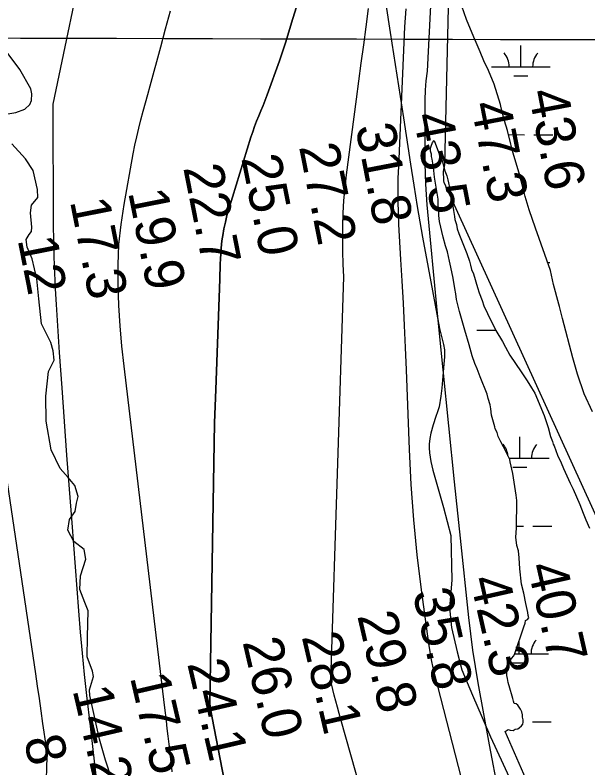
# Model space of a CAD drawing. Extents: x 3161665 to 3199565, y 885729 to 911164.
# Drawn here: x 3178214 to 3179188, y 895980 to 897260 of the extents above; entities that cross this region are included whole.
import ezdxf

# ---------------------------------------------------------------- set-up
doc = ezdxf.new("R2010")
doc.units = 0
for name, color, linetype in [('V-GRID-MAJR', 7, 'Continuous'), ('V-RIVR-EDGE', 7, 'Continuous'), ('V-RIVR-RANG', 7, 'Continuous'), ('V-SITE-VEGE', 7, 'Continuous'), ('V-TOPO-DPTH', 7, 'Continuous'), ('V-TOPO-MAJR', 7, 'Continuous'), ('V-TOPO-MINR', 7, 'Continuous'), ('V-TOPO-WATR', 7, 'Continuous'), ('V-WETL-SWMP', 7, 'Continuous')]:
    doc.layers.add(name, color=color, linetype=linetype)

msp = doc.modelspace()

# ---------------------------------------------------------------- linework, layer by layer
at = {"layer": 'V-GRID-MAJR'}
msp.add_spline([(3165896.843, 897258.21), (3171121.2120000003, 897241.873), (3176345.5840000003, 897226.295), (3181569.957, 897211.478), (3186794.333, 897197.42), (3192018.711, 897184.122), (3197243.091, 897171.584), (3197243.092, 897171.584)], degree=3, dxfattribs=at)
at = {"layer": 'V-RIVR-EDGE'}
for points in [[(3178201.617912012, 897091.790542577), (3178215.099333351, 897094.3652820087), (3178230.326984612, 897099.978457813), (3178239.0398621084, 897107.7811387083), (3178241.6651185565, 897114.7295141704), (3178242.127740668, 897126.0300290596), (3178240.844132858, 897134.2921075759), (3178221.800052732, 897167.374816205), (3178200.571841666, 897196.116133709)], [(3178378.34260989, 895960.3183127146), (3178367.556308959, 895992.9459230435), (3178357.647959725, 896029.048795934), (3178340.8782962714, 896102.9857240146), (3178340.467266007, 896112.5496824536), (3178347.04330509, 896135.1367394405), (3178345.76184694, 896144.2681710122), (3178336.2602286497, 896169.068379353), (3178336.777667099, 896202.5373971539), (3178338.191329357, 896246.8711784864), (3178332.576003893, 896261.2294766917), (3178323.937289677, 896283.4194762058), (3178324.8636087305, 896306.4551825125), (3178334.0627546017, 896335.1212619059), (3178331.494464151, 896351.210742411), (3178313.7060462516, 896364.7297828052), (3178303.322176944, 896384.3160224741), (3178306.408980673, 896402.1302362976), (3178316.006258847, 896416.01623892), (3178318.2151108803, 896430.3551901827), (3178321.285792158, 896441.6492560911), (3178315.2465384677, 896460.3553944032), (3178303.9782684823, 896473.8583123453), (3178290.54091518, 896489.1053105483), (3178275.405699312, 896520.8743161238), (3178266.8325497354, 896569.5795838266), (3178266.068530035, 896612.1800331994), (3178270.953155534, 896653.8971567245), (3178280.1297299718, 896673.4350290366), (3178278.429717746, 896689.0876833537), (3178274.5520235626, 896703.0070057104), (3178258.5485294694, 896735.2128374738), (3178254.3060227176, 896777.3872089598), (3178250.9124472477, 896811.3005767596), (3178242.7374299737, 896845.2257676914), (3178234.528018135, 896865.2413097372), (3178232.8215569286, 896878.2859048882), (3178238.059171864, 896886.9665374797), (3178241.5484072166, 896891.7393806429), (3178242.437107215, 896899.5614084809), (3178240.323915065, 896923.9086681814), (3178241.660189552, 896936.9457395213), (3178252.558272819, 896949.5244880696), (3178252.157990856, 896963.4352117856), (3178244.4133507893, 896995.6206217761), (3178231.857173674, 897015.6469121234), (3178208.4469813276, 897040.9161915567)]]:
    msp.add_lwpolyline(points, dxfattribs=at)
at = {"layer": 'V-SITE-VEGE'}
for p, q in [((3178844.216, 897278.5349999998), (3178851.311, 897230.0849999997)), ((3178851.311, 897230.0849999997), (3178874.412, 897085.0949999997)), ((3178874.412, 897085.0949999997), (3178885.9420000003, 897006.6939999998)), ((3178885.9420000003, 897006.6939999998), (3178891.607, 896970.5009999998)), ((3178891.607, 896970.5009999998), (3178897.52, 896934.3479999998)), ((3178897.52, 896934.3479999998), (3178906.453, 896882.4459999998)), ((3178906.453, 896882.4459999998), (3178915.9390000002, 896830.6369999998)), ((3178915.9390000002, 896830.6369999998), (3178935.467, 896727.1639999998)), ((3178935.467, 896727.1639999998), (3178938.8340000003, 896713.6019999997)), ((3178938.8340000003, 896713.6019999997), (3178942.434, 896700.0959999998)), ((3178942.434, 896700.0959999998), (3178943.948, 896690.9719999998)), ((3178943.948, 896690.9719999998), (3178944.1750000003, 896684.8829999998)), ((3178943.849, 896678.7659999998), (3178942.643, 896666.5229999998)), ((3178944.1750000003, 896684.8829999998), (3178943.849, 896678.7659999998)), ((3178942.643, 896666.5229999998), (3178939.536, 896625.3989999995)), ((3178939.536, 896625.3989999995), (3178937.955, 896611.7469999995)), ((3178937.955, 896611.7469999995), (3178934.693, 896593.6509999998)), ((3178932.008, 896585.5269999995), (3178928.9620000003, 896577.5349999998)), ((3178934.693, 896593.6509999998), (3178932.008, 896585.5269999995)), ((3178928.9620000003, 896577.5349999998), (3178924.588, 896563.5309999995)), ((3178924.588, 896563.5309999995), (3178920.6720000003, 896549.3219999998)), ((3178920.6720000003, 896549.3219999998), (3178918.835, 896539.9929999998)), ((3178918.835, 896539.9929999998), (3178917.936, 896530.5459999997)), ((3178917.936, 896530.5459999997), (3178917.858, 896524.2419999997)), ((3178917.858, 896524.2419999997), (3178918.401, 896515.9049999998)), ((3178918.401, 896515.9049999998), (3178920.596, 896500.9889999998)), ((3178920.596, 896500.9889999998), (3178924.017, 896486.2419999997)), ((3178924.017, 896486.2419999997), (3178933.071, 896454.4629999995)), ((3178933.071, 896454.4629999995), (3178942.393, 896422.8209999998)), ((3178942.393, 896422.8209999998), (3178954.708, 896374.8549999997)), ((3178954.708, 896374.8549999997), (3178956.631, 896299.1749999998)), ((3178956.631, 896299.1749999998), (3178954.808, 896279.3709999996)), ((3178954.808, 896279.3709999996), (3178952.639, 896252.2429999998)), ((3178952.639, 896252.2429999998), (3178955.894, 896218.6049999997)), ((3178955.894, 896218.6049999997), (3178965.657, 896177.3699999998)), ((3178965.657, 896177.3699999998), (3178973.25, 896146.9859999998)), ((3178973.25, 896146.9859999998), (3178991.693, 896103.5809999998)), ((3178991.693, 896103.5809999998), (3179007.964, 896065.6029999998)), ((3179007.964, 896065.6029999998), (3179022.069, 896033.0499999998)), ((3179022.069, 896033.0499999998), (3179043.7630000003, 895986.3879999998)), ((3179043.7630000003, 895986.3879999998), (3179069.799, 895929.9619999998))]:
    msp.add_line(p, q, dxfattribs=at)
at = {"layer": 'V-TOPO-DPTH'}
for points in [[(3178859.7052312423, 897811.8009133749), (3178683.971657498, 897246.9387973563), (3178674.1705732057, 897214.5114061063), (3178663.364810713, 897182.3625362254), (3178642.3309438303, 897124.2634451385), (3178638.9716953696, 897115.2234071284), (3178635.5116471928, 897106.2230984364), (3178631.9003994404, 897097.2823837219), (3178628.188351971, 897088.3813983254), (3178624.54341345, 897079.4579472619), (3178621.0883832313, 897070.4649463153), (3178617.918215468, 897061.3676205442), (3178614.937956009, 897052.2007448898), (3178577.3112899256, 896929.9501530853), (3178574.1741301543, 896918.887475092), (3178571.3690015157, 896907.7489882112), (3178569.061919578, 896896.4967879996), (3178567.0868687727, 896885.1687789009), (3178566.21151534, 896879.3909969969), (3178565.078478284, 896870.8807860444), (3178564.1503880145, 896862.3519970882), (3178563.5297179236, 896853.7953411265), (3178563.113994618, 896845.2201071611), (3178562.845206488, 896836.6311385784), (3178562.5667702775, 896828.0424909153), (3178562.27386195, 896819.4543246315), (3178561.9713055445, 896810.8664792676), (3178555.2151163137, 896623.5815065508), (3178552.7718726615, 896566.9030446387), (3178544.7785713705, 896089.8985583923), (3178545.67613638, 896083.7384648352), (3178546.640442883, 896077.5893959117), (3178547.7048616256, 896071.4568639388), (3178548.836021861, 896065.3353565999), (3178667.7391202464, 895449.9836645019)], [(3178367.6467745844, 895829.032779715), (3178346.644979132, 896011.4635693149), (3178345.5129858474, 896021.2999095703), (3178344.381500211, 896031.1363082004), (3178343.250776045, 896040.9727943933), (3178342.1205595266, 896050.8093389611), (3178336.1221828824, 896103.0324697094), (3178332.19636842, 896139.0001007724), (3178328.541420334, 896174.9936939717), (3178325.292771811, 896211.0262303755), (3178322.314989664, 896247.0847289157), (3178310.7941442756, 896396.8911518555), (3178306.436270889, 896454.1543789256), (3178302.1393138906, 896511.4221278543), (3178297.9337314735, 896568.6966595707), (3178293.789065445, 896625.9757131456), (3178289.466234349, 896686.3864560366), (3178287.592488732, 896713.4675927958), (3178285.8038284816, 896740.5541468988), (3178284.142796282, 896767.6488270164), (3178282.5668494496, 896794.7489244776), (3178281.2719958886, 896821.8593985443), (3178280.2666717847, 896848.9782854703), (3178279.6956418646, 896876.1097916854), (3178279.4141414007, 896903.2497107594), (3178278.92802394, 897108.7204964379), (3178395.3976408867, 897666.5492682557)], [(3178367.6467745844, 895829.032779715), (3178346.644979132, 896011.4635693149), (3178345.5129858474, 896021.2999095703), (3178344.381500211, 896031.1363082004), (3178343.250776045, 896040.9727943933), (3178342.1205595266, 896050.8093389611), (3178336.1221828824, 896103.0324697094), (3178332.19636842, 896139.0001007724), (3178328.541420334, 896174.9936939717), (3178325.292771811, 896211.0262303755), (3178322.314989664, 896247.0847289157), (3178310.7941442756, 896396.8911518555), (3178306.436270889, 896454.1543789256), (3178302.1393138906, 896511.4221278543), (3178297.9337314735, 896568.6966595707), (3178293.789065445, 896625.9757131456), (3178289.466234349, 896686.3864560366), (3178287.592488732, 896713.4675927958), (3178285.8038284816, 896740.5541468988), (3178284.142796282, 896767.6488270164), (3178282.5668494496, 896794.7489244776), (3178281.2719958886, 896821.8593985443), (3178280.2666717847, 896848.9782854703), (3178279.6956418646, 896876.1097916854), (3178279.4141414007, 896903.2497107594), (3178278.92802394, 897108.7204964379), (3178395.3976408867, 897666.5492682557)]]:
    msp.add_lwpolyline(points, dxfattribs=at)
at = {"layer": 'V-TOPO-MAJR'}
msp.add_lwpolyline([(3179035.989455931, 895938.8060119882), (3179020.7442605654, 896019.0504007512), (3179001.420908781, 896124.6958166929), (3178996.6939576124, 896152.2752988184), (3178992.379008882, 896179.9143991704), (3178988.6820638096, 896207.6429268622), (3178985.3971211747, 896235.4310727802), (3178970.943760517, 896370.6243904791), (3178960.904763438, 896466.0704746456), (3178951.0834504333, 896561.5385770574), (3178941.5886635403, 896657.0397068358), (3178932.311560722, 896752.5628548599), (3178914.687317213, 896937.3164966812), (3178913.2636323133, 896954.7909122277), (3178912.1622063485, 896972.2811576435), (3178911.5441687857, 896989.7951478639), (3178911.2483901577, 897007.324967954), (3178910.916835, 897115.7171421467), (3178911.4620824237, 897132.0551710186), (3178912.7916099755, 897148.3002159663), (3178915.2975577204, 897164.4057850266), (3178946.735314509, 897788.8579925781)], dxfattribs=at)
at = {"layer": 'V-TOPO-MINR'}
for points in [[(3178667.7391202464, 895449.9836645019), (3178548.836021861, 896065.3353565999), (3178547.7048616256, 896071.4568639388), (3178546.640442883, 896077.5893959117), (3178545.67613638, 896083.7384648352), (3178544.7785713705, 896089.8985583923), (3178552.7718726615, 896566.9030446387), (3178555.2151163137, 896623.5815065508), (3178561.9713055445, 896810.8664792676), (3178562.27386195, 896819.4543246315), (3178562.5667702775, 896828.0424909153), (3178562.845206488, 896836.6311385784), (3178563.113994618, 896845.2201071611), (3178563.5297179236, 896853.7953411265), (3178564.1503880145, 896862.3519970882), (3178565.078478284, 896870.8807860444), (3178566.21151534, 896879.3909969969), (3178567.0868687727, 896885.1687789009), (3178569.061919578, 896896.4967879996), (3178571.3690015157, 896907.7489882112), (3178574.1741301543, 896918.887475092), (3178577.3112899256, 896929.9501530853), (3178614.937956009, 897052.2007448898), (3178617.918215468, 897061.3676205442), (3178621.0883832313, 897070.4649463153), (3178624.54341345, 897079.4579472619), (3178628.188351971, 897088.3813983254), (3178631.9003994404, 897097.2823837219), (3178635.5116471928, 897106.2230984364), (3178638.9716953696, 897115.2234071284), (3178642.3309438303, 897124.2634451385), (3178663.364810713, 897182.3625362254), (3178674.1705732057, 897214.5114061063), (3178683.971657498, 897246.9387973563), (3178859.7052312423, 897811.8009133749)], [(3179385.048032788, 895912.3644955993), (3179295.625001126, 896183.773940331), (3179285.694839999, 896214.451649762), (3179275.979247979, 896245.1959345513), (3178943.2248445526, 896975.3493151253), (3178942.87839248, 896978.3821940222), (3178942.708202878, 896981.4300488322), (3178942.412640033, 896992.4549297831), (3178942.4329190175, 896994.1037838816), (3178942.771017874, 896997.3706990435), (3178943.771943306, 897002.2266306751), (3178944.291539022, 897005.4947278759), (3178963.4115114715, 897808.7301279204)], [(3178480.9039155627, 895973.2675758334), (3178480.216906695, 895980.8753054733), (3178478.9436278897, 895994.1289770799), (3178477.569486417, 896007.3715994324), (3178476.044050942, 896020.597647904), (3178474.417752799, 896033.8126471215), (3178472.7346574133, 896047.0216977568), (3178471.076725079, 896060.2338694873), (3178469.4565373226, 896073.4507228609), (3178467.861512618, 896086.6706973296), (3178399.175341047, 896662.8779320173), (3178395.5452310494, 896697.2678689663), (3178392.5343586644, 896731.7035516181), (3178390.4523426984, 896766.2078528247), (3178388.989564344, 896800.7578997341), (3178389.069485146, 896835.2615680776), (3178390.573258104, 896869.6585349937), (3178394.2128092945, 896903.8954497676), (3178399.27621264, 896938.025663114), (3178414.7563632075, 897023.8585975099), (3178417.592331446, 897038.4914065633), (3178420.680193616, 897053.0674222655), (3178424.145896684, 897067.5582479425), (3178427.8634936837, 897081.9922802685), (3178431.7696350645, 897096.3838331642), (3178435.6748807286, 897110.7756290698), (3178439.5787828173, 897125.1677894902), (3178443.48178919, 897139.5601929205), (3178461.4687669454, 897205.8997424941), (3178469.79144065, 897236.5211460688), (3178478.1391118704, 897267.1357171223)], [(3178947.3904141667, 895427.2841689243), (3178767.4978949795, 896062.2960431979), (3178764.634101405, 896072.6384239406), (3178761.852323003, 896083.0022982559), (3178759.1935673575, 896093.3984129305), (3178756.6168268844, 896103.8160211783), (3178752.0537582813, 896122.744802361), (3178751.450564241, 896126.6730779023), (3178751.0797413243, 896132.1041814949), (3178750.960596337, 896135.5592151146), (3178751.074421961, 896139.01442807), (3178751.308149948, 896142.4695147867), (3178751.427535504, 896144.1968852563), (3178751.54818184, 896145.924169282), (3178772.679201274, 896814.683563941), (3178771.911919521, 896836.3879522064), (3178771.3706923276, 896858.0962104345), (3178771.168546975, 896879.8102736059), (3178771.192456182, 896901.5282067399), (3178771.7861693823, 896923.220835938), (3178772.9117619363, 896944.8759726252), (3178774.835173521, 896966.4748705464), (3178777.2904644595, 896988.0362759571), (3178794.3535708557, 897116.7102760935), (3178798.4482173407, 897147.5813835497), (3178802.5440608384, 897178.452332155), (3178806.641699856, 897209.3230424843), (3178810.740535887, 897240.1935939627), (3178814.8778448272, 897271.0588808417)], [(3178992.131949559, 895887.7910867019), (3178928.11640779, 896136.4846342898), (3178924.862588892, 896150.1060809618), (3178921.9282714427, 896163.7902285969), (3178919.47320617, 896177.5684276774), (3178917.337642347, 896191.4093277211), (3178904.8973597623, 896282.5689786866), (3178897.6740625, 896342.1137294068), (3178891.637795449, 896401.7607585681), (3178887.3820737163, 896461.561205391), (3178884.3133821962, 896521.4639306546), (3178879.410120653, 896656.5817808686), (3178877.8865352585, 896694.5063480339), (3178876.166862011, 896732.4212589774), (3178874.1530569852, 896770.3216855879), (3178871.9431641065, 896808.212455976), (3178869.6862031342, 896844.4883976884), (3178868.532069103, 896864.2376449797), (3178867.477075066, 896883.9918128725), (3178866.570791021, 896903.7533616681), (3178865.7636469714, 896923.5198310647), (3178865.2725850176, 896943.2891089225), (3178865.1033683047, 896963.0572117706), (3178865.416919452, 896982.8235521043), (3178866.052315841, 897002.5887174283), (3178876.594392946, 897240.1366942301), (3178878.8689677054, 897270.5862286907)], [(3178263.126133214, 895828.5791070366), (3178268.3289927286, 895998.9416513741), (3178268.3553546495, 896000.345815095), (3178268.280399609, 896004.5569732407), (3178267.961709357, 896008.757147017), (3178267.4793203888, 896012.8475860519), (3178267.233761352, 896014.6594261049), (3178261.3075770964, 896055.6794660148), (3178258.244816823, 896076.790895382), (3178255.1653668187, 896097.8998798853), (3178252.0608822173, 896119.0051970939), (3178248.9397078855, 896140.1080694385), (3178149.456821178, 896809.9864307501)]]:
    msp.add_lwpolyline(points, dxfattribs=at)
at = {"layer": 'V-TOPO-WATR'}
msp.add_lwpolyline([(3178367.6467745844, 895829.032779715), (3178346.644979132, 896011.4635693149), (3178345.5129858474, 896021.2999095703), (3178344.381500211, 896031.1363082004), (3178343.250776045, 896040.9727943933), (3178342.1205595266, 896050.8093389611), (3178336.1221828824, 896103.0324697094), (3178332.19636842, 896139.0001007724), (3178328.541420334, 896174.9936939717), (3178325.292771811, 896211.0262303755), (3178322.314989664, 896247.0847289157), (3178310.7941442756, 896396.8911518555), (3178306.436270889, 896454.1543789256), (3178302.1393138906, 896511.4221278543), (3178297.9337314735, 896568.6966595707), (3178293.789065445, 896625.9757131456), (3178289.466234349, 896686.3864560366), (3178287.592488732, 896713.4675927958), (3178285.8038284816, 896740.5541468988), (3178284.142796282, 896767.6488270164), (3178282.5668494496, 896794.7489244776), (3178281.2719958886, 896821.8593985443), (3178280.2666717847, 896848.9782854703), (3178279.6956418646, 896876.1097916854), (3178279.4141414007, 896903.2497107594), (3178278.92802394, 897108.7204964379), (3178395.3976408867, 897666.5492682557)], dxfattribs=at)
at = {"layer": 'V-WETL-SWMP'}
for p, q in [((3179073.8022305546, 897172.0168936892), (3179073.901710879, 897208.0167555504)), ((3179023.8024287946, 897172.1550660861), (3179123.8020323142, 897171.8787212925)), ((3179061.7596369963, 897156.6191142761), (3179085.7595418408, 897156.5527915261)), ((3179052.630005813, 897056.6429637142), (3179080.075226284, 897056.5671199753)), ((3179096.075162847, 897056.5229048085), (3179128.0750359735, 897056.4344744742)), ((3179119.4387497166, 896839.2145151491), (3179122.8827373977, 896839.2049978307)), ((3178999.1562485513, 896724.1144723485), (3179031.1561216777, 896724.0260420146)), ((3179071.9636407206, 896506.6694467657), (3179072.063121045, 896542.6693086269)), ((3179053.833961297, 896506.7195473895), (3179121.963442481, 896506.531274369)), ((3179059.9210471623, 896491.2716673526), (3179083.9209520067, 896491.2053446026)), ((3179066.5971422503, 896391.2518383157), (3179078.2366364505, 896391.2196730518)), ((3179094.2365730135, 896391.175457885), (3179126.23644614, 896391.0870275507)), ((3179071.044345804, 896173.9957233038), (3179071.106871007, 896196.62229485)), ((3179063.394274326, 896174.0168639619), (3179121.044147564, 896173.8575509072)), ((3179059.0017522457, 896158.5979438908), (3179083.00165709, 896158.5316211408)), ((3179093.317278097, 896058.5017344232), (3179125.3171512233, 896058.4133040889))]:
    msp.add_line(p, q, dxfattribs=at)
for points in [[(3179129.291000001, 896802.0869999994), (3179124.281000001, 896825.4549999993), (3179098.897000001, 896897.5829999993), (3179088.113000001, 896928.7709999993), (3179081.154000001, 896951.5059999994), (3179077.996000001, 896962.5469999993), (3179071.080000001, 896991.1149999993), (3179060.330000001, 897026.8399999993), (3179056.543000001, 897040.4779999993), (3179050.885000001, 897063.8509999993), (3179045.822000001, 897080.0909999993), (3179040.154000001, 897102.1689999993), (3179038.902000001, 897108.0109999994), (3179028.141000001, 897142.4399999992), (3179018.595000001, 897165.8419999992), (3179010.940000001, 897182.1009999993), (3179004.575000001, 897197.7029999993), (3178996.296000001, 897217.2069999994), (3178993.743000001, 897222.4109999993), (3178981.652000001, 897252.3139999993), (3178973.397000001, 897275.0579999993)], [(3178945.725000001, 896867.6189999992), (3178941.948000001, 896882.5529999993), (3178935.666000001, 896909.1719999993), (3178934.443000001, 896918.9019999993), (3178934.467000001, 896922.1429999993), (3178933.292000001, 896938.3539999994), (3178933.355000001, 896946.7779999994), (3178927.155000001, 896984.4129999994), (3178925.337000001, 897001.2769999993), (3178922.847000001, 897014.9059999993), (3178921.584000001, 897019.4519999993), (3178921.613000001, 897023.3399999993), (3178920.356000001, 897028.5339999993), (3178920.395000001, 897033.7179999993), (3178921.067000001, 897036.9539999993), (3178923.708000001, 897043.4149999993), (3178926.324000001, 897046.6359999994), (3178937.128000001, 897018.0389999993), (3178940.310000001, 897010.2389999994), (3178944.735000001, 896995.2999999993), (3178947.912000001, 896986.8509999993), (3178949.8030000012, 896979.7079999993), (3178953.556000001, 896961.5329999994), (3178954.170000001, 896956.9919999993), (3178956.061000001, 896949.8489999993), (3178959.136000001, 896927.7909999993), (3178961.003000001, 896917.4079999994), (3178961.612000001, 896912.2179999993), (3178964.142000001, 896903.7739999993), (3178965.384000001, 896896.6359999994), (3178968.567000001, 896888.8349999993), (3178981.919000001, 896854.3869999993), (3178986.358000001, 896841.3919999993), (3178988.254000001, 896834.8969999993), (3178990.140000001, 896827.1059999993), (3178993.327000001, 896819.9529999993), (3179000.281000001, 896796.5699999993), (3179002.806000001, 896787.4779999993), (3179007.893000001, 896774.4779999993), (3179011.066000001, 896765.3819999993), (3179016.801000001, 896752.3769999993), (3179031.493000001, 896723.7509999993), (3179042.370000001, 896704.8759999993), (3179047.481000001, 896695.1159999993), (3179055.156000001, 896681.4489999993), (3179074.389000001, 896653.4379999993), (3179084.642000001, 896637.8069999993), (3179091.683000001, 896626.0889999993), (3179097.448000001, 896616.9719999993)], [(3179086.782000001, 895951.2219999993), (3179066.756000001, 895996.4339999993), (3179047.224000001, 896041.8699999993), (3179052.344000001, 896045.0499999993), (3179055.580000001, 896044.3779999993), (3179060.759000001, 896043.6909999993), (3179064.014000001, 896045.6109999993), (3179068.555000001, 896046.2249999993), (3179071.162000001, 896048.1499999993), (3179075.074000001, 896051.3609999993), (3179077.043000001, 896054.5869999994), (3179077.7150000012, 896057.8219999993), (3179077.744000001, 896061.7099999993), (3179076.4820000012, 896066.2559999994), (3179076.511000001, 896070.1449999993), (3179075.254000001, 896075.3389999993), (3179073.343000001, 896079.8899999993), (3179068.855000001, 896086.4039999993), (3179065.635000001, 896089.0209999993), (3179062.399000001, 896089.6929999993), (3179061.132000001, 896093.5909999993), (3179059.870000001, 896098.1369999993), (3179059.251000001, 896102.0299999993), (3179054.816000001, 896115.6729999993), (3179052.297000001, 896125.4129999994), (3179051.049000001, 896131.9029999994), (3179049.792000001, 896137.0969999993), (3179049.879000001, 896148.7619999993), (3179050.566000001, 896153.9419999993), (3179057.7860000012, 896166.2009999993), (3179061.709000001, 896170.7089999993), (3179063.682000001, 896174.5819999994), (3179078.926000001, 896219.8339999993), (3179080.918000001, 896226.2999999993), (3179081.600000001, 896230.8319999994), (3179084.850000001, 896232.1039999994), (3179087.467000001, 896235.3249999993), (3179086.200000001, 896239.2229999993), (3179085.5900000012, 896244.4119999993), (3179082.462000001, 896259.3409999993), (3179078.704000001, 896276.8679999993), (3179074.932000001, 896292.4499999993), (3179071.885000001, 896318.3959999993), (3179070.730000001, 896337.1989999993), (3179069.521000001, 896348.8739999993), (3179066.997000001, 896357.9659999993), (3179065.159000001, 896372.2369999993), (3179066.571000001, 896387.7809999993), (3179066.920000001, 896434.4409999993), (3179065.692000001, 896443.5229999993), (3179060.135000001, 896480.5049999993), (3179055.7490000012, 896500.6289999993), (3179055.130000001, 896504.5219999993), (3179053.210000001, 896507.7769999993), (3179044.273000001, 896525.9899999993), (3179039.800000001, 896534.4479999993), (3179035.331000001, 896543.5549999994), (3179033.435000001, 896550.0499999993), (3179030.244000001, 896556.5549999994), (3179029.620000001, 896559.7999999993), (3179023.938000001, 896579.9329999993), (3179022.719000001, 896590.3109999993), (3179021.476000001, 896597.4499999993), (3179018.313000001, 896607.8429999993), (3179016.427000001, 896615.6339999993), (3179004.332000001, 896644.8879999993), (3178999.250000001, 896658.5359999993), (3178995.429000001, 896667.6369999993), (3178990.990000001, 896680.6319999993), (3178985.946000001, 896699.4649999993), (3178978.353000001, 896724.1489999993), (3178969.518000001, 896755.9709999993), (3178964.484000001, 896776.0989999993), (3178963.260000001, 896785.8289999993), (3178961.384000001, 896794.9169999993), (3178958.922000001, 896812.4329999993), (3178954.526000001, 896831.2609999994), (3178952.660000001, 896841.6439999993), (3178948.888000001, 896857.2259999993), (3178945.725000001, 896867.6189999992)], [(3179195.719000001, 896585.1299999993), (3179181.690000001, 896615.6949999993), (3179170.277000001, 896649.4809999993), (3179162.060000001, 896677.4099999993), (3179144.414000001, 896744.2939999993), (3179139.379000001, 896764.4229999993), (3179138.112000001, 896768.3209999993), (3179129.291000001, 896802.0869999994)], [(3179097.448000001, 896616.9719999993), (3179113.368000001, 896579.2649999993), (3179120.342000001, 896558.4739999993), (3179124.119000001, 896543.5389999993), (3179127.296000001, 896535.0909999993), (3179128.558000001, 896530.5449999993), (3179130.478000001, 896527.2899999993), (3179136.194000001, 896511.6929999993), (3179142.578000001, 896498.6839999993), (3179146.3940000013, 896488.9339999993), (3179157.875000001, 896464.2209999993), (3179162.981000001, 896453.8129999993), (3179173.805000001, 896427.8089999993), (3179179.526000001, 896412.8599999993), (3179183.980000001, 896401.8089999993), (3179190.354000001, 896387.5039999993)]]:
    msp.add_lwpolyline(points, dxfattribs=at)
for centre, radius, start, end in [((3179018.560825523, 897172.6443560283), 35.24628790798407, 359.069845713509, 40.613504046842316), ((3179129.0462596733, 897172.3390340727), 35.24628790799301, 139.06984290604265, 180.61350123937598), ((3179016.7222356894, 896507.2969091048), 35.24628790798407, 5.4250459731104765, 40.613504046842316), ((3179127.2076698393, 896506.9915871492), 35.24628790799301, 139.06984290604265, 180.61350123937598), ((3179126.2883749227, 896174.3178636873), 35.24628790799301, 139.06984290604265, 180.61350123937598)]:
    msp.add_arc(centre, radius, start, end, dxfattribs=at)

# ---------------------------------------------------------------- texts
at = {"layer": 'V-RIVR-RANG'}
for s, height, rotation, p in [('43.6', 66.99999999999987, 280.8983257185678, (3179086.3987225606, 897129.302346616)), ('47.3', 66.99999999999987, 280.8983257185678, (3178988.5988261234, 897108.3381921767)), ('43.5', 66.99999999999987, 280.8983257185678, (3178890.449826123, 897089.1871921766)), ('31.8', 66.99999999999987, 280.8983257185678, (3178792.3008261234, 897070.0351921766)), ('27.2', 67.00000000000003, 281.1827777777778, (3178696.4189282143, 897036.3756814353)), ('25.0', 67.00000000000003, 281.1827777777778, (3178598.321085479, 897016.9659101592)), ('22.7', 67.00000000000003, 281.1827777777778, (3178499.6093555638, 897000.6613941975)), ('19.9', 67.00000000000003, 281.1827777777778, (3178405.9110376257, 896958.9972931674)), ('17.3', 67.00000000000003, 281.1827777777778, (3178306.99467865, 896943.7268623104)), ('12', 67.00000000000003, 281.1827777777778, (3178217.951671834, 896878.5145751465)), ('40.7', 67, 282.79832571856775, (3179084.411681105, 896323.0208445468)), ('42.3', 67, 282.79832571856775, (3178986.950681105, 896300.6308445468)), ('35.8', 67, 282.79832571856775, (3178889.4886811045, 896278.2408445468)), ('29.8', 67, 283.07916666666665, (3178795.3774131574, 896238.8596529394)), ('26.0', 67, 283.07916666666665, (3178600.395720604, 896194.3365895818)), ('28.1', 67, 283.07916666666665, (3178700.960733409, 896203.3658841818)), ('24.1', 67, 283.07916666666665, (3178506.2775036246, 896157.5591376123)), ('17.5', 67, 283.07916666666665, (3178408.9945812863, 896134.3983276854)), ('14.2', 67, 283.07916666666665, (3178311.4141961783, 896112.52220097)), ('8', 67, 283.07916666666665, (3178228.2794091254, 896028.4674068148))]:
    msp.add_text(s, height=height, rotation=rotation, dxfattribs=at).set_placement(p)

doc.saveas('drawing.dxf')
